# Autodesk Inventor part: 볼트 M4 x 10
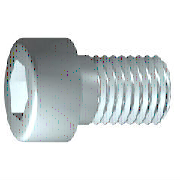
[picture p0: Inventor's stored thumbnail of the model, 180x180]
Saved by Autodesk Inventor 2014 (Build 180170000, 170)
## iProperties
IsCustomPart: 0
Created: 2012-02
Part Number: 볼트 M4 x 10
Material: 스테인리스강
Description: 6각 소켓 머리 캡 나사
Document SubType Name: Modeling
Standard: ISO 4762
Designer: mduedu
Standard Revision: Fourth edition 2004-03-01
Standards Organization: ISO
Language: ko-KR
Size Designation: M4 x 10
Categories: <MemberInstance><Categories><Category DisplayName="조임쇠" InternalName="e4da775c-781d-43d5-af7c-5136215cf5a6" Mnemonic="FSTN"><Category DisplayName="볼트" InternalN
Density: 8.08 g/cm^3
Appearance: 반광택
Mass: 2.09412 g
Surface Area: 3.0572 cm^2
Volume: 0.259174 cm^3
Author: mduedu
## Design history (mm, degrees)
sketch "스케치1"
  geometry: L1 (-1, 0)-(10, 0); L2 (10, 0)-(10, 2); L3 (10, 2)-(1.75, 2); L4 (1.75, 2)-(1.32, 2); L5 (1.32, 2)-(0, 2); L6 (0, 2)-(0, 3.5); L7 (0, 3.5)-(-4, 3.5); L8 (-4, 3.5)-(-4, 1.732); L9 (-4, 1.732)-(-2, 1.732); L10 (-2, 1.732)-(-1, 0); L11 (-6.8, 0)-(12.8, 0) reference; L12 (0, -0.7)-(0, 4.2) reference; L13 (1.75, 2)-(0, 2)
  constraints: 22 end point, 6 parallel, 2 collinear, 2 perpendicular, 1 horizontal, 1 point on line
  dimensions: "d1" = 8.25 distance from line of L3.end L2 (= GEL); "d2" = 0.42952 distance of L4.end L3.end (computed from GAL); "d3" = 4 distance between parallel lines of L8 L6 (= KOH); "d4" = 2 distance of L8.end L9.end (= INTI); "d5" = 60 deg angle of L10 L1; "d6" = 4 diameter of L3 L1 (= GD); "d7" = 4 diameter of L5 L1 (= BDM); "d8" = 3.4641 diameter of L9 L1 (= 1.1547 x SW); "d9" = 7 diameter of L7 L1 (= KOD); "d26" = 10 distance between parallel lines of L12 L2 (= NLG)
revolve "본체" sketch "스케치1" stored, may be unused: angle "d10" = 90 deg
sketch "스케치2"
  geometry: L1 (0, -4.9)-(0, 4.9) reference; L2 (-4.9, 0)-(4.9, 0) reference; L3 (1.732, 0)-(0.866, -1.5); L4 (0.866, -1.5)-(-0.866, -1.5); L5 (-0.866, -1.5)-(-1.732, 0); L6 (-1.732, 0)-(-0.866, 1.5); L7 (-0.866, 1.5)-(0.866, 1.5); L8 (0.866, 1.5)-(1.732, 0); 2 further points
  constraints: 12 end point, 1 coincident, 1 horizontal alignment, 1 point on line, 12 other
extrude "슬롯" join sketch "스케치2" stored distance "d11" = 10; taper "d12" = 0 deg
workplane "Work Plane1"
fillet "Fillet2" dims "d30" = 0.1 (= R)
body "Solid1"
fillet "모깎기1" dims "d17" = 0.4 (= RR)
feature "스레드" dims "d13" = 8.25 (= GEL), "d14" = 0
chamfer "모따기1" distance "d15" = 0.42941 (= -0.5 x SPD + 0.5 x GD); stored, may be unused: second distance "d16" = 0.42941 (= GUL), angle "d27" = 45 deg
other parameters: "GD" = 4 [user parameter; used in 2 equation terms], "NLG" = 10 [user parameter; used in 1 equation term], "GEL" = 8.25 [user parameter; used in 2 equation terms], "KOD" = 7 [user parameter; used in 1 equation term], "KOH" = 4 [user parameter; used in 1 equation term], "INTI" = 2 [user parameter; used in 1 equation term], "GAL" = 0.42941 (= 0.61345 x PTC) [user parameter; used in 1 equation term], "GUL" = 0.42941 (= 0.61345 x PTC) [user parameter; used in 1 equation term], "BDM" = 4 (= NND) [user parameter; used in 1 equation term], "SW" = 3 [user parameter; used in 2 equation terms], "RR" = 0.4 [user parameter; used in 1 equation term], "SPD" = 3.14117 (= NND - 1.2269 x PTC) [user parameter; used in 1 equation term], "d19" = 0, "d28" = 0, "d29" = 0, "R" = 0.1 [user parameter; used in 1 equation term], "TOA" = 30 deg [user parameter], "GD1" = 3.14117 (= THREADDIA - 1.2269 x PTC) [user parameter], "THREADDIA" = 4 [user parameter; used in 1 equation term], "FAWI" = 45 deg [user parameter], "TPU" = 14.28571 (computed from PTC) [user parameter], "PTC" = 0.7 [user parameter; used in 5 equation terms], "NND" = 4 [user parameter; used in 2 equation terms], "E0" = 3.465 (= 1.155 x SW) [user parameter]
